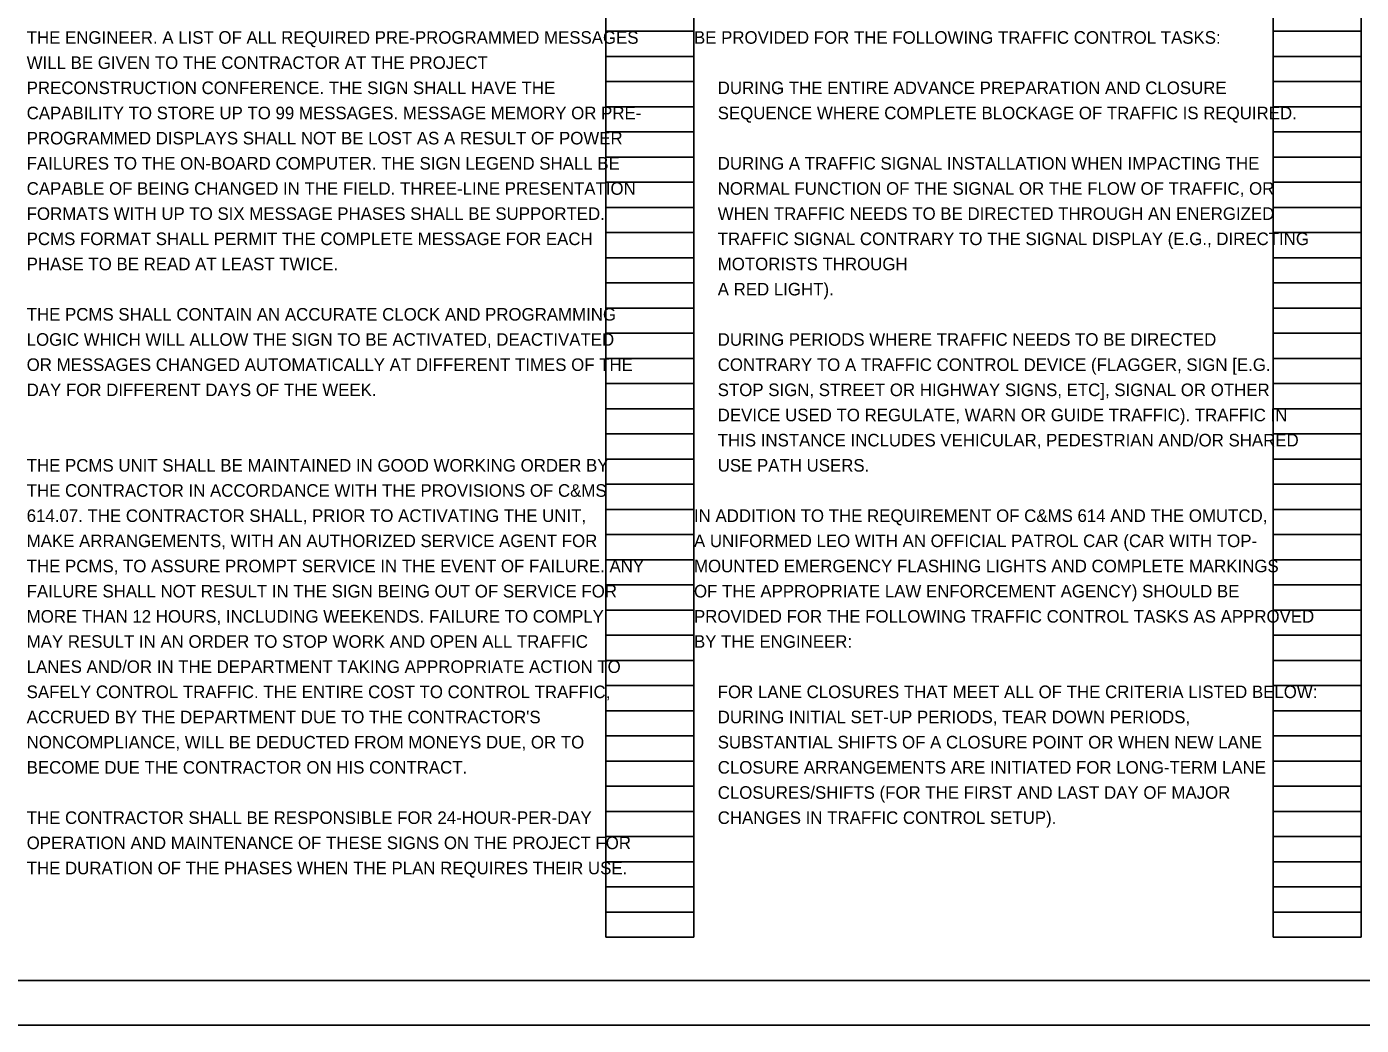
# Model space of a CAD drawing. Extents: x -18.5 to 46, y -14.2 to 42.5.
# Drawn here: x 9.82 to 24.66, y 0 to 11.11 of the extents above; entities that cross this region are included whole.
import ezdxf

# ---------------------------------------------------------------- set-up
doc = ezdxf.new("R2010")
doc.units = 0
for name, color, linetype in [('SH_Border', 7, 'Continuous'), ('SH_Cut_Line', 7, 'Continuous'), ('SH_Data', 7, 'Continuous'), ('SH_Text', 7, 'Continuous')]:
    doc.layers.add(name, color=color, linetype=linetype)

msp = doc.modelspace()

# ---------------------------------------------------------------- linework, layer by layer
at = {"layer": 'SH_Border'}
msp.add_lwpolyline([(1.5, 21.5), (33.5, 21.5), (33.5, 0.5), (1.5, 0.5)], close=True, dxfattribs=at)
at = {"layer": 'SH_Cut_Line'}
msp.add_lwpolyline([(0, 0), (34, 0), (34, 22), (0, 22)], close=True, dxfattribs=at)
at = {"layer": 'SH_Data'}
for p, q in [((16.26, 0.98), (16.26, 21.14)), ((17.24, 0.98), (17.24, 21.14)), ((23.68, 0.98), (23.68, 21.14)), ((24.66, 0.98), (24.66, 21.14)), ((16.26, 11.06), (17.24, 11.06)), ((23.68, 11.06), (24.66, 11.06)), ((16.26, 10.78), (17.24, 10.78)), ((23.68, 10.78), (24.66, 10.78)), ((16.26, 10.5), (17.24, 10.5)), ((23.68, 10.5), (24.66, 10.5)), ((16.26, 10.22), (17.24, 10.22)), ((23.68, 10.22), (24.66, 10.22)), ((16.26, 9.94), (17.24, 9.94)), ((23.68, 9.94), (24.66, 9.94)), ((16.26, 9.66), (17.24, 9.66)), ((23.68, 9.66), (24.66, 9.66)), ((16.26, 9.38), (17.24, 9.38)), ((23.68, 9.38), (24.66, 9.38)), ((16.26, 9.1), (17.24, 9.1)), ((23.68, 9.1), (24.66, 9.1)), ((16.26, 8.82), (17.24, 8.82)), ((23.68, 8.82), (24.66, 8.82)), ((16.26, 8.54), (17.24, 8.54)), ((23.68, 8.54), (24.66, 8.54)), ((16.26, 8.26), (17.24, 8.26)), ((23.68, 8.26), (24.66, 8.26)), ((16.26, 7.98), (17.24, 7.98)), ((23.68, 7.98), (24.66, 7.98)), ((16.26, 7.7), (17.24, 7.7)), ((23.68, 7.7), (24.66, 7.7)), ((16.26, 7.42), (17.24, 7.42)), ((23.68, 7.42), (24.66, 7.42)), ((16.26, 7.14), (17.24, 7.14)), ((23.68, 7.14), (24.66, 7.14)), ((16.26, 6.86), (17.24, 6.86)), ((23.68, 6.86), (24.66, 6.86)), ((16.26, 6.58), (17.24, 6.58)), ((23.68, 6.58), (24.66, 6.58)), ((16.26, 6.3), (17.24, 6.3)), ((23.68, 6.3), (24.66, 6.3)), ((16.26, 6.02), (17.24, 6.02)), ((23.68, 6.02), (24.66, 6.02)), ((16.26, 5.74), (17.24, 5.74)), ((23.68, 5.74), (24.66, 5.74)), ((16.26, 5.46), (17.24, 5.46)), ((23.68, 5.46), (24.66, 5.46)), ((16.26, 5.18), (17.24, 5.18)), ((23.68, 5.18), (24.66, 5.18)), ((16.26, 4.9), (17.24, 4.9)), ((23.68, 4.9), (24.66, 4.9)), ((16.26, 4.62), (17.24, 4.62)), ((23.68, 4.62), (24.66, 4.62)), ((16.26, 4.34), (17.24, 4.34)), ((23.68, 4.34), (24.66, 4.34)), ((16.26, 4.06), (17.24, 4.06)), ((23.68, 4.06), (24.66, 4.06)), ((16.26, 3.78), (17.24, 3.78)), ((23.68, 3.78), (24.66, 3.78)), ((16.26, 3.5), (17.24, 3.5)), ((23.68, 3.5), (24.66, 3.5)), ((16.26, 3.22), (17.24, 3.22)), ((23.68, 3.22), (24.66, 3.22)), ((16.26, 2.94), (17.24, 2.94)), ((23.68, 2.94), (24.66, 2.94)), ((16.26, 2.66), (17.24, 2.66)), ((23.68, 2.66), (24.66, 2.66)), ((16.26, 2.38), (17.24, 2.38)), ((23.68, 2.38), (24.66, 2.38)), ((16.26, 2.1), (17.24, 2.1)), ((23.68, 2.1), (24.66, 2.1)), ((16.26, 1.82), (17.24, 1.82)), ((23.68, 1.82), (24.66, 1.82)), ((16.26, 1.54), (17.24, 1.54)), ((23.68, 1.54), (24.66, 1.54)), ((16.26, 1.26), (17.24, 1.26)), ((23.68, 1.26), (24.66, 1.26)), ((16.26, 0.98), (17.24, 0.98)), ((23.68, 0.98), (24.66, 0.98))]:
    msp.add_line(p, q, dxfattribs=at)

# ---------------------------------------------------------------- texts
at = {"layer": 'SH_Text'}
for s, p in [('THE ENGINEER. A LIST OF ALL REQUIRED PRE-PROGRAMMED MESSAGES ', (9.82, 10.92)), ('BE PROVIDED FOR THE FOLLOWING TRAFFIC CONTROL TASKS:', (17.24, 10.92)), ('WILL BE GIVEN TO THE CONTRACTOR AT THE PROJECT ', (9.82, 10.64)), ('PRECONSTRUCTION CONFERENCE. THE SIGN SHALL HAVE THE ', (9.82, 10.36)), ('DURING THE ENTIRE ADVANCE PREPARATION AND CLOSURE ', (17.504, 10.36)), ('CAPABILITY TO STORE UP TO 99 MESSAGES. MESSAGE MEMORY OR PRE-', (9.82, 10.08)), ('SEQUENCE WHERE COMPLETE BLOCKAGE OF TRAFFIC IS REQUIRED.', (17.504, 10.08)), ('PROGRAMMED DISPLAYS SHALL NOT BE LOST AS A RESULT OF POWER ', (9.82, 9.8)), ('FAILURES TO THE ON-BOARD COMPUTER. THE SIGN LEGEND SHALL BE ', (9.82, 9.52)), ('DURING A TRAFFIC SIGNAL INSTALLATION WHEN IMPACTING THE ', (17.504, 9.52)), ('CAPABLE OF BEING CHANGED IN THE FIELD. THREE-LINE PRESENTATION ', (9.82, 9.24)), ('NORMAL FUNCTION OF THE SIGNAL OR THE FLOW OF TRAFFIC, OR ', (17.504, 9.24)), ('FORMATS WITH UP TO SIX MESSAGE PHASES SHALL BE SUPPORTED. ', (9.82, 8.96)), ('WHEN TRAFFIC NEEDS TO BE DIRECTED THROUGH AN ENERGIZED ', (17.504, 8.96)), ('PCMS FORMAT SHALL PERMIT THE COMPLETE MESSAGE FOR EACH ', (9.82, 8.68)), ('TRAFFIC SIGNAL CONTRARY TO THE SIGNAL DISPLAY (E.G., DIRECTING ', (17.504, 8.68)), ('PHASE TO BE READ AT LEAST TWICE.', (9.82, 8.4)), ('MOTORISTS THROUGH', (17.504, 8.4)), ('A RED LIGHT).', (17.504, 8.12)), ('THE PCMS SHALL CONTAIN AN ACCURATE CLOCK AND PROGRAMMING ', (9.82, 7.84)), ('LOGIC WHICH WILL ALLOW THE SIGN TO BE ACTIVATED, DEACTIVATED ', (9.82, 7.56)), ('DURING PERIODS WHERE TRAFFIC NEEDS TO BE DIRECTED ', (17.504, 7.56)), ('OR MESSAGES CHANGED AUTOMATICALLY AT DIFFERENT TIMES OF THE ', (9.82, 7.28)), ('CONTRARY TO A TRAFFIC CONTROL DEVICE (FLAGGER, SIGN [E.G. ', (17.504, 7.28)), ('DAY FOR DIFFERENT DAYS OF THE WEEK.', (9.82, 7)), ('STOP SIGN, STREET OR HIGHWAY SIGNS, ETC], SIGNAL OR OTHER ', (17.504, 7)), ('DEVICE USED TO REGULATE, WARN OR GUIDE TRAFFIC). TRAFFIC IN ', (17.504, 6.72)), ('THIS INSTANCE INCLUDES VEHICULAR, PEDESTRIAN AND/OR SHARED ', (17.504, 6.44)), ('THE PCMS UNIT SHALL BE MAINTAINED IN GOOD WORKING ORDER BY ', (9.82, 6.16)), ('USE PATH USERS.', (17.504, 6.16)), ('THE CONTRACTOR IN ACCORDANCE WITH THE PROVISIONS OF C&MS ', (9.82, 5.88)), ('614.07. THE CONTRACTOR SHALL, PRIOR TO ACTIVATING THE UNIT, ', (9.82, 5.6)), ('IN ADDITION TO THE REQUIREMENT OF C&MS 614 AND THE OMUTCD, ', (17.24, 5.6)), ('MAKE ARRANGEMENTS, WITH AN AUTHORIZED SERVICE AGENT FOR ', (9.82, 5.32)), ('A UNIFORMED LEO WITH AN OFFICIAL PATROL CAR (CAR WITH TOP-', (17.24, 5.32)), ('THE PCMS, TO ASSURE PROMPT SERVICE IN THE EVENT OF FAILURE. ANY ', (9.82, 5.04)), ('MOUNTED EMERGENCY FLASHING LIGHTS AND COMPLETE MARKINGS ', (17.24, 5.04)), ('FAILURE SHALL NOT RESULT IN THE SIGN BEING OUT OF SERVICE FOR ', (9.82, 4.76)), ('OF THE APPROPRIATE LAW ENFORCEMENT AGENCY) SHOULD BE ', (17.24, 4.76)), ('MORE THAN 12 HOURS, INCLUDING WEEKENDS. FAILURE TO COMPLY ', (9.82, 4.48)), ('PROVIDED FOR THE FOLLOWING TRAFFIC CONTROL TASKS AS APPROVED ', (17.24, 4.48)), ('MAY RESULT IN AN ORDER TO STOP WORK AND OPEN ALL TRAFFIC ', (9.82, 4.2)), ('BY THE ENGINEER:', (17.24, 4.2)), ('LANES AND/OR IN THE DEPARTMENT TAKING APPROPRIATE ACTION TO ', (9.82, 3.92)), ('SAFELY CONTROL TRAFFIC. THE ENTIRE COST TO CONTROL TRAFFIC, ', (9.82, 3.64)), ('FOR LANE CLOSURES THAT MEET ALL OF THE CRITERIA LISTED BELOW: ', (17.504, 3.64)), ("ACCRUED BY THE DEPARTMENT DUE TO THE CONTRACTOR'S ", (9.82, 3.36)), ('DURING INITIAL SET-UP PERIODS, TEAR DOWN PERIODS, ', (17.504, 3.36)), ('NONCOMPLIANCE, WILL BE DEDUCTED FROM MONEYS DUE, OR TO ', (9.82, 3.08)), ('SUBSTANTIAL SHIFTS OF A CLOSURE POINT OR WHEN NEW LANE ', (17.504, 3.08)), ('BECOME DUE THE CONTRACTOR ON HIS CONTRACT.', (9.82, 2.8)), ('CLOSURE ARRANGEMENTS ARE INITIATED FOR LONG-TERM LANE ', (17.504, 2.8)), ('CLOSURES/SHIFTS (FOR THE FIRST AND LAST DAY OF MAJOR ', (17.504, 2.52)), ('THE CONTRACTOR SHALL BE RESPONSIBLE FOR 24-HOUR-PER-DAY ', (9.82, 2.24)), ('CHANGES IN TRAFFIC CONTROL SETUP).', (17.504, 2.24)), ('OPERATION AND MAINTENANCE OF THESE SIGNS ON THE PROJECT FOR ', (9.82, 1.96)), ('THE DURATION OF THE PHASES WHEN THE PLAN REQUIRES THEIR USE.', (9.82, 1.68))]:
    msp.add_text(s, height=0.14, dxfattribs=at).set_placement(p)

doc.saveas('drawing.dxf')
